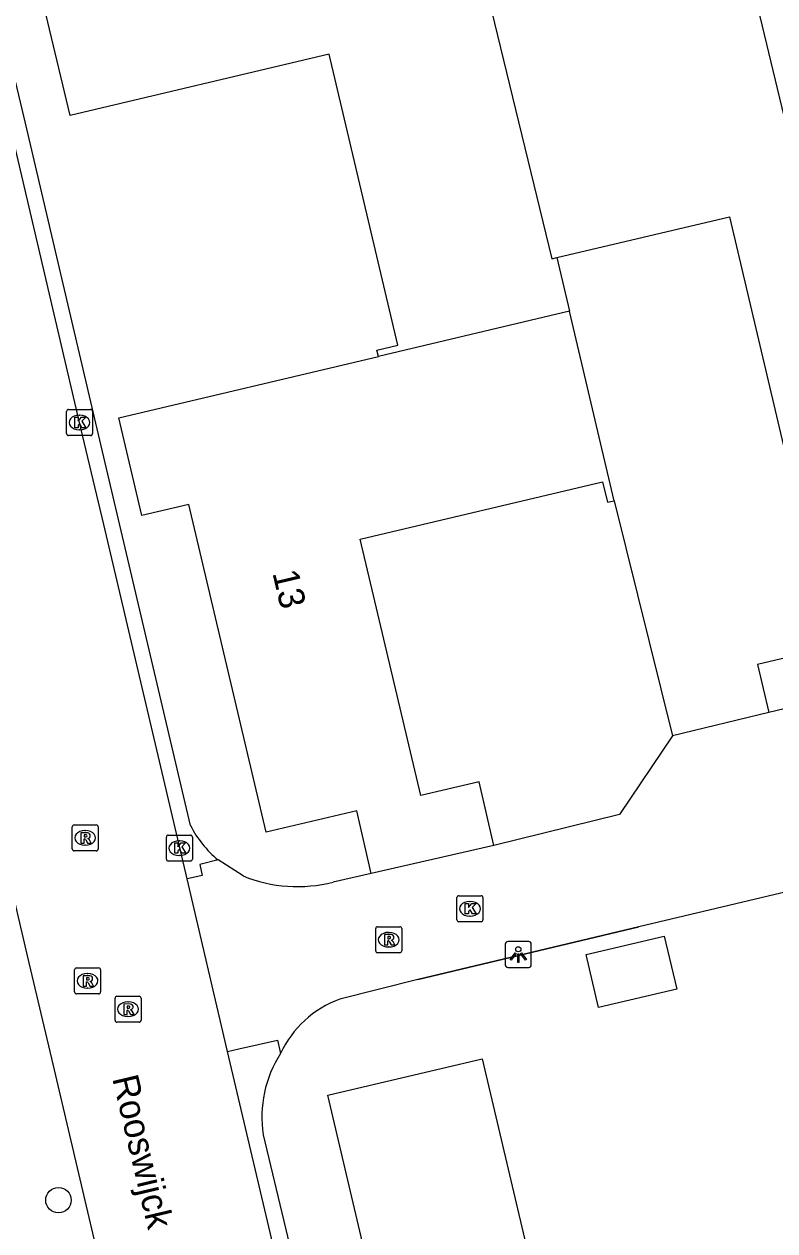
# Model space of a CAD drawing. Extents: x 157663 to 158496, y 379212 to 380934.
# Drawn here: x 158179.72 to 158208.58, y 380702.61 to 380749 of the extents above; entities that cross this region are included whole.
import ezdxf

# ---------------------------------------------------------------- set-up
doc = ezdxf.new("R2010")
doc.units = 0
for name, color, linetype in [('IMGEO_Boom', 7, 'Continuous'), ('IMGEO_Hek', 7, 'Continuous'), ('IMGEO_Kolk', 7, 'Continuous'), ('IMGEO_Lichtpunt', 7, 'Continuous'), ('IMGEO_Openbare_ruimte_label', 7, 'Continuous'), ('IMGEO_Pand', 7, 'Continuous'), ('IMGEO_Pand_nummerreeks', 7, 'Continuous'), ('IMGEO_Rijbaan_lokaal_open', 7, 'Continuous'), ('IMGEO_Rioolput', 7, 'Continuous'), ('IMGEO_Voetpad_open', 7, 'Continuous')]:
    doc.layers.add(name, color=color, linetype=linetype)

msp = doc.modelspace()

# ---------------------------------------------------------------- linework, layer by layer
at = {"layer": 'IMGEO_Boom'}
msp.add_circle((158181.044, 380703.789), 0.489, dxfattribs=at)
at = {"layer": 'IMGEO_Hek'}
for points in [[(158182.48, 380733.655), (158179.773, 380745.194)], [(158204.649, 380721.641), (158202.616, 380718.62), (158197.776, 380717.426)], [(158194.857, 380712.273), (158203.35, 380714.302)]]:
    msp.add_lwpolyline(points, dxfattribs=at)
at = {"layer": 'IMGEO_Kolk'}
for p, q in [((158181.428, 380734.183), (158182.28, 380734.183)), ((158181.353, 380733.257), (158181.353, 380734.109)), ((158181.841, 380733.963), (158181.866, 380733.963)), ((158182.354, 380734.109), (158182.354, 380733.257)), ((158181.864, 380733.403), (158181.839, 380733.403)), ((158182.28, 380733.183), (158181.428, 380733.183)), ((158185.192, 380716.897), (158185.192, 380717.749)), ((158185.267, 380717.823), (158186.119, 380717.823)), ((158185.68, 380717.603), (158185.705, 380717.603)), ((158186.193, 380717.749), (158186.193, 380716.897)), ((158185.703, 380717.043), (158185.678, 380717.043)), ((158186.119, 380716.823), (158185.267, 380716.823)), ((158196.361, 380714.567), (158196.361, 380715.419)), ((158196.436, 380715.493), (158197.288, 380715.493)), ((158196.849, 380715.273), (158196.874, 380715.273)), ((158197.362, 380715.419), (158197.362, 380714.567)), ((158196.872, 380714.713), (158196.847, 380714.713)), ((158197.288, 380714.493), (158196.436, 380714.493))]:
    msp.add_line(p, q, dxfattribs=at)
for points in [[(158181.428, 380734.183), (158182.28, 380734.183)], [(158181.353, 380733.257), (158181.353, 380734.109)], [(158181.674, 380733.883), (158181.797, 380733.883), (158181.797, 380733.732), (158181.927, 380733.883), (158182.091, 380733.883), (158181.945, 380733.732), (158182.098, 380733.483), (158181.946, 380733.483), (158181.861, 380733.647), (158181.797, 380733.58), (158181.797, 380733.483), (158181.674, 380733.483), (158181.674, 380733.883)], [(158182.354, 380734.109), (158182.354, 380733.257)], [(158182.28, 380733.183), (158181.428, 380733.183)], [(158185.192, 380716.897), (158185.192, 380717.749)], [(158185.267, 380717.823), (158186.119, 380717.823)], [(158185.513, 380717.523), (158185.636, 380717.523), (158185.636, 380717.372), (158185.766, 380717.523), (158185.93, 380717.523), (158185.784, 380717.372), (158185.937, 380717.123), (158185.785, 380717.123), (158185.7, 380717.287), (158185.636, 380717.22), (158185.636, 380717.123), (158185.513, 380717.123), (158185.513, 380717.523)], [(158186.193, 380717.749), (158186.193, 380716.897)], [(158186.119, 380716.823), (158185.267, 380716.823)], [(158196.361, 380714.567), (158196.361, 380715.419)], [(158196.436, 380715.493), (158197.288, 380715.493)], [(158196.682, 380715.193), (158196.805, 380715.193), (158196.805, 380715.042), (158196.935, 380715.193), (158197.099, 380715.193), (158196.953, 380715.042), (158197.106, 380714.793), (158196.954, 380714.793), (158196.869, 380714.957), (158196.805, 380714.89), (158196.805, 380714.793), (158196.682, 380714.793), (158196.682, 380715.193)], [(158197.362, 380715.419), (158197.362, 380714.567)], [(158197.288, 380714.493), (158196.436, 380714.493)]]:
    msp.add_lwpolyline(points, dxfattribs=at)
for centre, start, end in [((158181.43, 380734.107), 91.552, 178.448), ((158181.43, 380734.107), 91.552, 178.448), ((158182.278, 380734.107), 1.552, 88.448), ((158182.278, 380734.107), 1.552, 88.448), ((158181.43, 380733.259), 181.552, 268.448), ((158181.43, 380733.259), 181.552, 268.448), ((158182.278, 380733.259), 271.552, 358.448), ((158182.278, 380733.259), 271.552, 358.448), ((158185.269, 380717.747), 91.552, 178.448), ((158185.269, 380717.747), 91.552, 178.448), ((158186.117, 380717.747), 1.552, 88.448), ((158186.117, 380717.747), 1.552, 88.448), ((158185.269, 380716.899), 181.552, 268.448), ((158185.269, 380716.899), 181.552, 268.448), ((158186.117, 380716.899), 271.552, 358.448), ((158186.117, 380716.899), 271.552, 358.448), ((158196.438, 380715.417), 91.552, 178.448), ((158196.438, 380715.417), 91.552, 178.448), ((158197.286, 380715.417), 1.552, 88.448), ((158197.286, 380715.417), 1.552, 88.448), ((158196.438, 380714.569), 181.552, 268.448), ((158196.438, 380714.569), 181.552, 268.448), ((158197.286, 380714.569), 271.552, 358.448), ((158197.286, 380714.569), 271.552, 358.448)]:
    msp.add_arc(centre, 0.0765, start, end, dxfattribs=at)
for centre, major_axis, ratio, start_param, end_param in [((158181.84, 380733.683), (-0.387, 0.002), 0.722429, 4.712389, 7.853982), ((158181.865, 380733.683), (-0.39, 0.002), 0.717154, 1.570796, 4.712389), ((158185.679, 380717.323), (-0.387, 0.002), 0.722429, 4.712389, 7.853982), ((158185.704, 380717.323), (-0.39, 0.002), 0.717154, 1.570796, 4.712389), ((158196.848, 380714.993), (-0.387, 0.002), 0.722429, 4.712389, 7.853982), ((158196.873, 380714.993), (-0.39, 0.002), 0.717154, 1.570796, 4.712389)]:
    msp.add_ellipse(centre, major_axis=major_axis, ratio=ratio, start_param=start_param, end_param=end_param, dxfattribs=at)
at = {"layer": 'IMGEO_Lichtpunt'}
for p, q in [((158198.221, 380713.637), (158198.221, 380712.83)), ((158198.221, 380713.637), (158198.221, 380712.83)), ((158199.123, 380713.732), (158198.315, 380713.732)), ((158199.123, 380713.732), (158198.315, 380713.732)), ((158199.217, 380712.83), (158199.217, 380713.637)), ((158199.217, 380712.83), (158199.217, 380713.637)), ((158198.315, 380712.736), (158199.123, 380712.736)), ((158198.315, 380712.736), (158199.123, 380712.736))]:
    msp.add_line(p, q, dxfattribs=at)
for points in [[(158198.595, 380713.301), (158198.634, 380713.273), (158198.446, 380713.011), (158198.408, 380713.038), (158198.595, 380713.301)], [(158198.807, 380713.273), (158198.845, 380713.3), (158199.032, 380713.038), (158198.993, 380713.01), (158198.807, 380713.273)], [(158198.697, 380713.253), (158198.744, 380713.253), (158198.744, 380712.931), (158198.697, 380712.931), (158198.697, 380713.253)]]:
    msp.add_lwpolyline(points, dxfattribs=at)
msp.add_circle((158198.72, 380713.435), 0.0994, dxfattribs=at)
for centre, start, end in [((158198.315, 380713.637), 90, 180), ((158198.315, 380713.637), 90, 180), ((158199.123, 380713.637), 0, 90), ((158199.123, 380713.637), 0, 90), ((158198.315, 380712.83), 180, 270), ((158198.315, 380712.83), 180, 270), ((158199.123, 380712.83), 270, 0), ((158199.123, 380712.83), 270, 360)]:
    msp.add_arc(centre, 0.0946, start, end, dxfattribs=at)
at = {"layer": 'IMGEO_Pand'}
for points in [[(158193.343, 380736.22), (158193.284, 380736.466), (158194.088, 380736.656), (158191.445, 380747.84), (158181.498, 380745.49), (158180.424, 380750), (158180.113, 380751.304), (158192.898, 380754.334), (158192.482, 380756.093), (158196.194, 380756.973)], [(158215.641, 380743.56), (158215.604, 380743.715), (158209.698, 380742.319), (158207.856, 380750), (158207.04, 380753.401), (158197.57, 380751.156)], [(158197.57, 380751.156), (158197.315, 380751.096), (158197.581, 380750), (158200.009, 380739.978), (158200.203, 380740.024)], [(158200.203, 380740.024), (158206.837, 380741.591), (158209.391, 380730.781), (158219.202, 380733.118), (158220.561, 380727.367), (158207.912, 380724.377), (158208.356, 380722.534)], [(158200.203, 380740.024), (158200.692, 380737.958)], [(158200.692, 380737.958), (158193.343, 380736.22)], [(158202.41, 380730.678), (158200.692, 380737.958)], [(158193.064, 380716.348), (158192.512, 380718.762), (158189.029, 380717.938), (158186.053, 380730.534), (158184.252, 380730.109), (158183.365, 380733.862), (158193.343, 380736.22)], [(158197.776, 380717.426), (158197.215, 380719.877), (158194.977, 380719.344), (158192.647, 380729.205), (158201.961, 380731.406), (158202.148, 380730.616), (158202.41, 380730.678)], [(158202.41, 380730.678), (158204.649, 380721.641)], [(158208.356, 380722.534), (158204.649, 380721.641)], [(158197.776, 380717.426), (158193.064, 380716.348)], [(158201.808, 380711.191), (158201.326, 380713.231), (158204.333, 380713.941), (158204.815, 380711.901), (158201.808, 380711.191)], [(158193.605, 380691.158), (158192.731, 380694.858), (158194.365, 380695.244), (158191.394, 380707.821), (158197.33, 380709.224), (158199.643, 380699.435), (158208.911, 380701.625), (158208.77, 380702.222), (158209.098, 380702.3)]]:
    msp.add_lwpolyline(points, dxfattribs=at)
at = {"layer": 'IMGEO_Rijbaan_lokaal_open'}
for points in [[(158185.989, 380716.141), (158182.786, 380729.769), (158181.899, 380733.467), (158177.214, 380753.475)], [(158173.522, 380740.18), (158179.901, 380712.918), (158180.777, 380709.24), (158193.622, 380654.491)], [(158219.966, 380725.316), (158208.356, 380722.534)], [(158204.649, 380721.641), (158202.616, 380718.62), (158197.776, 380717.426)], [(158221.618, 380718.692), (158217.464, 380717.666), (158208.809, 380715.596), (158203.35, 380714.302), (158194.857, 380712.273), (158191.858, 380711.513)], [(158187.177, 380716.869), (158186.477, 380716.695), (158186.566, 380716.268), (158186.407, 380716.227), (158185.989, 380716.141)], [(158188.141, 380716.252), (158187.177, 380716.869)], [(158187.544, 380709.501), (158185.989, 380716.141)], [(158193.064, 380716.348), (158191.598, 380716.019)], [(158187.544, 380709.501), (158187.973, 380709.61), (158189.46, 380709.935), (158189.579, 380709.428)], [(158200.331, 380655.409), (158196.861, 380670.504), (158195.977, 380674.186), (158192.851, 380687.32), (158191.285, 380693.957), (158190.247, 380698.042), (158187.544, 380709.501)]]:
    msp.add_lwpolyline(points, dxfattribs=at)
for centre, radius, start, end in [((158190.22, 380721.341), 5.497, 247.775, 284.5132), ((158193.211, 380707.746), 4.002, 109.755, 155.1542)]:
    msp.add_arc(centre, radius, start, end, dxfattribs=at)
at = {"layer": 'IMGEO_Rioolput'}
for p, q in [((158181.572, 380717.29), (158181.572, 380718.142)), ((158181.647, 380718.216), (158182.499, 380718.216)), ((158182.06, 380717.996), (158182.085, 380717.996)), ((158182.573, 380718.142), (158182.573, 380717.29)), ((158182.499, 380717.216), (158181.647, 380717.216)), ((158182.083, 380717.436), (158182.058, 380717.436)), ((158193.239, 380713.377), (158193.239, 380714.229)), ((158193.314, 380714.303), (158194.166, 380714.303)), ((158194.24, 380714.229), (158194.24, 380713.377)), ((158193.727, 380714.083), (158193.752, 380714.083)), ((158194.166, 380713.303), (158193.314, 380713.303)), ((158193.75, 380713.523), (158193.725, 380713.523)), ((158181.662, 380711.793), (158181.662, 380712.645)), ((158181.737, 380712.719), (158182.589, 380712.719)), ((158182.15, 380712.499), (158182.175, 380712.499)), ((158182.663, 380712.645), (158182.663, 380711.793)), ((158182.173, 380711.939), (158182.148, 380711.939)), ((158182.589, 380711.719), (158181.737, 380711.719)), ((158183.218, 380710.705), (158183.218, 380711.557)), ((158183.293, 380711.631), (158184.145, 380711.631)), ((158184.219, 380711.557), (158184.219, 380710.705)), ((158183.706, 380711.411), (158183.731, 380711.411)), ((158184.145, 380710.631), (158183.293, 380710.631)), ((158183.729, 380710.851), (158183.704, 380710.851))]:
    msp.add_line(p, q, dxfattribs=at)
for points in [[(158181.572, 380717.29), (158181.572, 380718.142)], [(158181.647, 380718.216), (158182.499, 380718.216)], [(158182.573, 380718.142), (158182.573, 380717.29)], [(158182.161, 380717.914), (158181.909, 380717.916), (158181.909, 380717.516)], [(158181.909, 380717.516), (158182.033, 380717.516), (158182.033, 380717.678), (158182.044, 380717.678)], [(158182.087, 380717.835), (158182.033, 380717.835), (158182.033, 380717.754)], [(158182.033, 380717.754), (158182.085, 380717.754)], [(158182.091, 380717.649), (158182.162, 380717.516), (158182.302, 380717.516), (158182.237, 380717.642)], [(158182.499, 380717.216), (158181.647, 380717.216)], [(158193.239, 380713.377), (158193.239, 380714.229)], [(158193.314, 380714.303), (158194.166, 380714.303)], [(158194.24, 380714.229), (158194.24, 380713.377)], [(158193.828, 380714.001), (158193.576, 380714.003), (158193.576, 380713.603)], [(158193.576, 380713.603), (158193.7, 380713.603), (158193.7, 380713.765), (158193.711, 380713.765)], [(158193.754, 380713.922), (158193.7, 380713.922), (158193.7, 380713.841)], [(158193.7, 380713.841), (158193.752, 380713.841)], [(158194.166, 380713.303), (158193.314, 380713.303)], [(158193.758, 380713.736), (158193.829, 380713.603), (158193.969, 380713.603), (158193.904, 380713.729)], [(158181.662, 380711.793), (158181.662, 380712.645)], [(158181.737, 380712.719), (158182.589, 380712.719)], [(158182.251, 380712.417), (158181.999, 380712.419), (158181.999, 380712.019)], [(158182.663, 380712.645), (158182.663, 380711.793)], [(158181.999, 380712.019), (158182.123, 380712.019), (158182.123, 380712.181), (158182.134, 380712.181)], [(158182.177, 380712.338), (158182.123, 380712.338), (158182.123, 380712.257)], [(158182.123, 380712.257), (158182.175, 380712.257)], [(158182.181, 380712.152), (158182.252, 380712.019), (158182.392, 380712.019), (158182.327, 380712.145)], [(158182.589, 380711.719), (158181.737, 380711.719)], [(158183.218, 380710.705), (158183.218, 380711.557)], [(158183.293, 380711.631), (158184.145, 380711.631)], [(158184.219, 380711.557), (158184.219, 380710.705)], [(158183.807, 380711.329), (158183.555, 380711.331), (158183.555, 380710.931)], [(158183.555, 380710.931), (158183.679, 380710.931), (158183.679, 380711.093), (158183.69, 380711.093)], [(158183.733, 380711.25), (158183.679, 380711.25), (158183.679, 380711.169)], [(158183.679, 380711.169), (158183.731, 380711.169)], [(158183.737, 380711.064), (158183.808, 380710.931), (158183.948, 380710.931), (158183.883, 380711.057)], [(158184.145, 380710.631), (158183.293, 380710.631)]]:
    msp.add_lwpolyline(points, dxfattribs=at)
for centre, radius, start, end in [((158181.649, 380718.14), 0.0765, 91.552, 178.448), ((158181.649, 380718.14), 0.0765, 91.552, 178.448), ((158182.497, 380718.14), 0.0765, 1.552, 88.448), ((158182.497, 380718.14), 0.0765, 1.552, 88.448), ((158182.043, 380717.625), 0.0533, 26.0293, 88.6989), ((158182.069, 380717.943), 0.19, 274.7715, 282.9687), ((158182.093, 380717.739), 0.0964, 77.0061, 93.1865), ((158182.107, 380717.796), 0.0378, 276.6634, 79.6772), ((158182.16, 380717.804), 0.109, 350.3612, 89.416), ((158182.158, 380717.804), 0.112, 277.5842, 350.9817), ((158182.142, 380717.589), 0.108, 29.5134, 73.7905), ((158181.649, 380717.292), 0.0765, 181.552, 268.448), ((158181.649, 380717.292), 0.0765, 181.552, 268.448), ((158182.497, 380717.292), 0.0765, 271.552, 358.448), ((158182.497, 380717.292), 0.0765, 271.552, 358.448), ((158193.316, 380714.227), 0.0765, 91.552, 178.448), ((158193.316, 380714.227), 0.0765, 91.552, 178.448), ((158194.164, 380714.227), 0.0765, 1.552, 88.448), ((158194.164, 380714.227), 0.0765, 1.552, 88.448), ((158193.71, 380713.712), 0.0533, 26.0293, 88.6989), ((158193.736, 380714.03), 0.19, 274.7715, 282.9687), ((158193.76, 380713.826), 0.0964, 77.0061, 93.1865), ((158193.774, 380713.883), 0.0378, 276.6634, 79.6772), ((158193.827, 380713.891), 0.109, 350.3612, 89.416), ((158193.825, 380713.891), 0.112, 277.5842, 350.9817), ((158193.809, 380713.676), 0.108, 29.5134, 73.7905), ((158193.316, 380713.379), 0.0765, 181.552, 268.448), ((158193.316, 380713.379), 0.0765, 181.552, 268.448), ((158194.164, 380713.379), 0.0765, 271.552, 358.448), ((158194.164, 380713.379), 0.0765, 271.552, 358.448), ((158181.739, 380712.643), 0.0765, 91.552, 178.448), ((158181.739, 380712.643), 0.0765, 91.552, 178.448), ((158182.25, 380712.307), 0.109, 350.3612, 89.416), ((158182.587, 380712.643), 0.0765, 1.552, 88.448), ((158182.587, 380712.643), 0.0765, 1.552, 88.448), ((158182.133, 380712.128), 0.0533, 26.0293, 88.6989), ((158182.159, 380712.446), 0.19, 274.7715, 282.9687), ((158182.183, 380712.242), 0.0964, 77.0061, 93.1865), ((158182.197, 380712.299), 0.0378, 276.6634, 79.6772), ((158182.248, 380712.307), 0.112, 277.5842, 350.9817), ((158182.232, 380712.092), 0.108, 29.5134, 73.7905), ((158181.739, 380711.795), 0.0765, 181.552, 268.448), ((158181.739, 380711.795), 0.0765, 181.552, 268.448), ((158182.587, 380711.795), 0.0765, 271.552, 358.448), ((158182.587, 380711.795), 0.0765, 271.552, 358.448), ((158183.295, 380711.555), 0.0765, 91.552, 178.448), ((158183.295, 380711.555), 0.0765, 91.552, 178.448), ((158184.143, 380711.555), 0.0765, 1.552, 88.448), ((158184.143, 380711.555), 0.0765, 1.552, 88.448), ((158183.689, 380711.04), 0.0533, 26.0293, 88.6989), ((158183.715, 380711.358), 0.19, 274.7715, 282.9687), ((158183.739, 380711.154), 0.0964, 77.0061, 93.1865), ((158183.753, 380711.211), 0.0378, 276.6634, 79.6772), ((158183.806, 380711.219), 0.109, 350.3612, 89.416), ((158183.804, 380711.219), 0.112, 277.5842, 350.9817), ((158183.788, 380711.004), 0.108, 29.5134, 73.7905), ((158183.295, 380710.707), 0.0765, 181.552, 268.448), ((158183.295, 380710.707), 0.0765, 181.552, 268.448), ((158184.143, 380710.707), 0.0765, 271.552, 358.448), ((158184.143, 380710.707), 0.0765, 271.552, 358.448)]:
    msp.add_arc(centre, radius, start, end, dxfattribs=at)
for centre, major_axis, ratio, start_param, end_param in [((158182.059, 380717.716), (-0.387, 0.002), 0.722429, 4.712389, 7.853982), ((158182.084, 380717.716), (-0.39, 0.002), 0.717154, 1.570796, 4.712389), ((158193.726, 380713.803), (-0.387, 0.002), 0.722429, 4.712389, 7.853982), ((158193.751, 380713.803), (-0.39, 0.002), 0.717154, 1.570796, 4.712389), ((158182.149, 380712.219), (-0.387, 0.002), 0.722429, 4.712389, 7.853982), ((158182.174, 380712.219), (-0.39, 0.002), 0.717154, 1.570796, 4.712389), ((158183.705, 380711.131), (-0.387, 0.002), 0.722429, 4.712389, 7.853982), ((158183.73, 380711.131), (-0.39, 0.002), 0.717154, 1.570796, 4.712389)]:
    msp.add_ellipse(centre, major_axis=major_axis, ratio=ratio, start_param=start_param, end_param=end_param, dxfattribs=at)
at = {"layer": 'IMGEO_Voetpad_open'}
for points in [[(158186.115, 380718.194), (158182.48, 380733.655), (158179.773, 380745.194), (158177.781, 380753.546)], [(158188.916, 380706.299), (158197.453, 380670.646), (158200.837, 380655.951)]]:
    msp.add_lwpolyline(points, dxfattribs=at)
for centre, radius, start, end in [((158189.979, 380720.203), 4.356, 207.4718, 229.9532), ((158193.362, 380706.992), 4.499, 147.2171, 188.8562)]:
    msp.add_arc(centre, radius, start, end, dxfattribs=at)

# ---------------------------------------------------------------- texts
at = {"layer": 'IMGEO_Openbare_ruimte_label'}
msp.add_text('Rooswijck', height=1, rotation=283.2996, dxfattribs=at).set_placement((158183.108, 380708.478))
at = {"layer": 'IMGEO_Pand_nummerreeks'}
msp.add_text('13', height=1, rotation=283.2932, dxfattribs=at).set_placement((158189.264, 380727.902))

doc.saveas('drawing.dxf')
